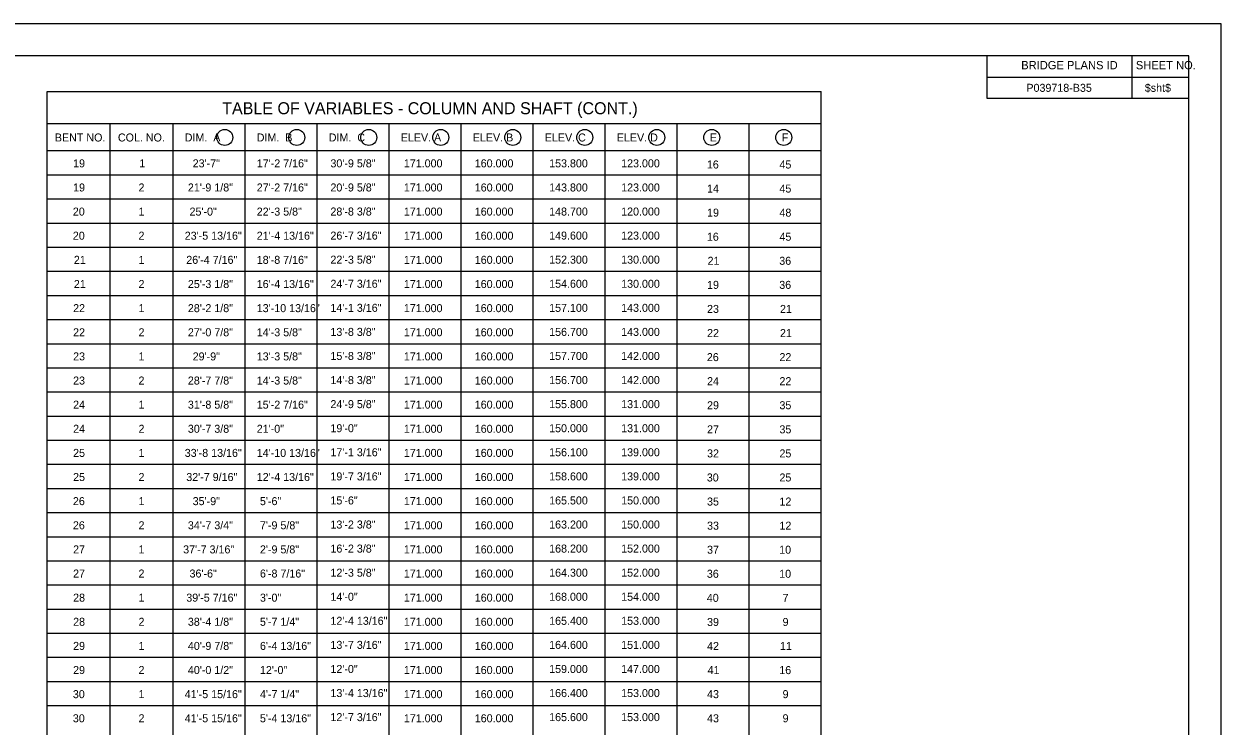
# Model space of a CAD drawing. Extents: x -133.1 to -97, y -1.7 to 20.3.
# Drawn here: x -115.84 to -97.14, y 9.34 to 20.31 of the extents above; entities that cross this region are included whole.
import ezdxf

# ---------------------------------------------------------------- set-up
doc = ezdxf.new("R2010")
doc.units = 0
for name, color, linetype in [('BR_BORDER LINES', 7, 'Continuous'), ('BR_TABLE LINES', 7, 'Continuous'), ('BR_TEXT', 7, 'Continuous'), ('Level 31', 7, 'Continuous')]:
    doc.layers.add(name, color=color, linetype=linetype)

msp = doc.modelspace()

# ---------------------------------------------------------------- linework, layer by layer
at = {"layer": 'BR_BORDER LINES'}
for p, q in [((-97.642, 19.809), (-131.308, 19.809)), ((-100.794, 19.142), (-100.794, 19.809)), ((-98.528, 19.142), (-98.528, 19.809)), ((-97.642, -1.191), (-97.642, 19.809)), ((-100.794, 19.479), (-97.642, 19.479)), ((-98.528, 19.479), (-97.642, 19.479)), ((-97.642, 19.142), (-100.794, 19.142))]:
    msp.add_line(p, q, dxfattribs=at)
at = {"layer": 'BR_TABLE LINES'}
for p, q in [((-115.482, 4.001), (-115.482, 19.253)), ((-115.482, 19.253), (-103.387, 19.253)), ((-103.387, 4.001), (-103.387, 19.253)), ((-115.482, 18.753), (-103.387, 18.753)), ((-114.497, 4.001), (-114.497, 18.753)), ((-113.512, 4.001), (-113.512, 18.753)), ((-112.387, 4.001), (-112.387, 18.753)), ((-111.262, 4.001), (-111.262, 18.753)), ((-110.137, 4.001), (-110.137, 18.753)), ((-109.012, 4.001), (-109.012, 18.753)), ((-107.887, 4.001), (-107.887, 18.753)), ((-106.762, 4.001), (-106.762, 18.753)), ((-105.637, 4.001), (-105.637, 18.753)), ((-104.512, 4.001), (-104.512, 18.753)), ((-115.482, 18.329), (-103.387, 18.329)), ((-115.482, 17.951), (-103.387, 17.951)), ((-115.482, 17.574), (-103.387, 17.574)), ((-115.482, 17.197), (-103.387, 17.197)), ((-115.482, 16.82), (-103.387, 16.82)), ((-115.482, 16.443), (-103.387, 16.443)), ((-115.482, 16.066), (-103.387, 16.066)), ((-115.482, 15.689), (-103.387, 15.689)), ((-115.482, 15.312), (-103.387, 15.312)), ((-115.482, 14.935), (-103.387, 14.935)), ((-115.482, 14.558), (-103.387, 14.558)), ((-115.482, 14.181), (-103.387, 14.181)), ((-115.482, 13.804), (-103.387, 13.804)), ((-115.482, 13.427), (-103.387, 13.427)), ((-115.482, 13.05), (-103.387, 13.05)), ((-115.482, 12.673), (-103.387, 12.673)), ((-115.482, 12.296), (-103.387, 12.296)), ((-115.482, 11.919), (-103.387, 11.919)), ((-115.482, 11.542), (-103.387, 11.542)), ((-115.482, 11.165), (-103.387, 11.165)), ((-115.482, 10.788), (-103.387, 10.788)), ((-115.482, 10.411), (-103.387, 10.411)), ((-115.482, 10.034), (-103.387, 10.034)), ((-115.482, 9.657), (-103.387, 9.657))]:
    msp.add_line(p, q, dxfattribs=at)
at = {"layer": 'BR_TEXT'}
for centre in [(-112.706, 18.535), (-111.581, 18.535), (-110.456, 18.535), (-109.331, 18.535), (-108.206, 18.535), (-107.081, 18.535), (-105.956, 18.535), (-105.097, 18.535), (-103.972, 18.535)]:
    msp.add_circle(centre, 0.125, dxfattribs=at)
at = {"layer": 'Level 31'}
msp.add_lwpolyline([(-133.141, -1.691), (-97.141, -1.691), (-97.141, 20.309), (-133.141, 20.309)], close=True, dxfattribs=at)

# ---------------------------------------------------------------- texts
at = {"layer": 'BR_TEXT'}
for s, height, p in [('BRIDGE PLANS ID', 0.13, (-100.263, 19.6)), ('SHEET NO.', 0.13, (-98.472, 19.6)), ('P039718-B35', 0.125, (-100.182, 19.248)), ('$sht$', 0.125, (-98.332, 19.248)), ('TABLE OF VARIABLES - COLUMN AND SHAFT (CONT.)', 0.1875, (-112.746, 18.898))]:
    msp.add_text(s, height=height, dxfattribs=at).set_placement(p)
for s, p in [('BENT NO.', (-115.36, 18.472)), ('COL. NO.', (-114.375, 18.472)), ('DIM.  A', (-113.331, 18.472)), ('DIM.  B', (-112.206, 18.472)), ('DIM.  C', (-111.081, 18.472)), ('ELEV. A', (-109.956, 18.472)), ('ELEV. B', (-108.831, 18.472)), ('ELEV. C', (-107.706, 18.472)), ('ELEV. D', (-106.581, 18.472)), ('E', (-105.128, 18.472)), ('F', (-104.003, 18.472)), ('19', (-115.075, 18.068)), ('1', (-114.041, 18.068)), ('23\'-7"', (-113.207, 18.068)), ('17\'-2 7/16"', (-112.206, 18.068)), ('30\'-9 5/8"', (-111.055, 18.068)), ('171.000', (-109.908, 18.068)), ('160.000', (-108.8, 18.068)), ('153.800', (-107.638, 18.068)), ('123.000', (-106.513, 18.068)), ('16', (-105.174, 18.05)), ('45', (-104.04, 18.05)), ('19', (-115.075, 17.691)), ('2', (-114.053, 17.691)), ('21\'-9 1/8"', (-113.282, 17.691)), ('27\'-2 7/16"', (-112.206, 17.691)), ('20\'-9 5/8"', (-111.055, 17.691)), ('171.000', (-109.908, 17.691)), ('160.000', (-108.8, 17.691)), ('143.800', (-107.638, 17.691)), ('123.000', (-106.513, 17.691)), ('14', (-105.171, 17.674)), ('45', (-104.04, 17.674)), ('20', (-115.079, 17.314)), ('1', (-114.053, 17.314)), ('25\'-0"', (-113.256, 17.314)), ('22\'-3 5/8"', (-112.206, 17.314)), ('28\'-8 3/8"', (-111.055, 17.315)), ('171.000', (-109.908, 17.314)), ('160.000', (-108.8, 17.314)), ('148.700', (-107.638, 17.315)), ('120.000', (-106.513, 17.315)), ('19', (-105.171, 17.298)), ('48', (-104.04, 17.298)), ('20', (-115.079, 16.937)), ('2', (-114.053, 16.937)), ('23\'-5 13/16"', (-113.331, 16.937)), ('21\'-4 13/16"', (-112.206, 16.937)), ('26\'-7 3/16"', (-111.055, 16.939)), ('171.000', (-109.908, 16.937)), ('160.000', (-108.8, 16.937)), ('149.600', (-107.638, 16.939)), ('123.000', (-106.513, 16.939)), ('16', (-105.174, 16.921)), ('45', (-104.04, 16.921)), ('21', (-115.063, 16.56)), ('1', (-114.053, 16.56)), ('26\'-4 7/16"', (-113.307, 16.56)), ('18\'-8 7/16"', (-112.206, 16.56)), ('22\'-3 5/8"', (-111.055, 16.563)), ('171.000', (-109.908, 16.56)), ('160.000', (-108.8, 16.56)), ('152.300', (-107.638, 16.563)), ('130.000', (-106.513, 16.563)), ('21', (-105.163, 16.545)), ('36', (-104.043, 16.545)), ('21', (-115.063, 16.182)), ('2', (-114.053, 16.182)), ('25\'-3 1/8"', (-113.282, 16.182)), ('16\'-4 13/16"', (-112.206, 16.182)), ('24\'-7 3/16"', (-111.055, 16.186)), ('171.000', (-109.908, 16.182)), ('160.000', (-108.8, 16.182)), ('154.600', (-107.638, 16.186)), ('130.000', (-106.513, 16.186)), ('19', (-105.171, 16.169)), ('36', (-104.043, 16.169)), ('22', (-115.075, 15.805)), ('1', (-114.053, 15.805)), ('28\'-2 1/8"', (-113.282, 15.805)), ('13\'-10 13/16"', (-112.206, 15.805)), ('14\'-1 3/16"', (-111.055, 15.81)), ('171.000', (-109.908, 15.805)), ('160.000', (-108.8, 15.805)), ('157.100', (-107.638, 15.81)), ('143.000', (-106.513, 15.81)), ('23', (-105.171, 15.793)), ('21', (-104.032, 15.793)), ('22', (-115.075, 15.428)), ('2', (-114.053, 15.428)), ('27\'-0 7/8"', (-113.282, 15.428)), ('14\'-3 5/8"', (-112.206, 15.428)), ('13\'-8 3/8"', (-111.055, 15.434)), ('171.000', (-109.908, 15.428)), ('160.000', (-108.8, 15.428)), ('156.700', (-107.638, 15.434)), ('143.000', (-106.513, 15.434)), ('22', (-105.171, 15.416)), ('21', (-104.032, 15.416)), ('23', (-115.075, 15.051)), ('1', (-114.053, 15.051)), ('29\'-9"', (-113.207, 15.051)), ('13\'-3 5/8"', (-112.206, 15.051)), ('15\'-8 3/8"', (-111.055, 15.058)), ('171.000', (-109.908, 15.051)), ('160.000', (-108.8, 15.051)), ('157.700', (-107.638, 15.058)), ('142.000', (-106.513, 15.058)), ('26', (-105.174, 15.04)), ('22', (-104.04, 15.04)), ('23', (-115.075, 14.674)), ('2', (-114.053, 14.674)), ('28\'-7 7/8"', (-113.282, 14.674)), ('14\'-3 5/8"', (-112.206, 14.674)), ('14\'-8 3/8"', (-111.055, 14.681)), ('171.000', (-109.908, 14.674)), ('160.000', (-108.8, 14.674)), ('156.700', (-107.638, 14.681)), ('142.000', (-106.513, 14.681)), ('24', (-105.171, 14.664)), ('22', (-104.04, 14.664)), ('24', (-115.075, 14.297)), ('1', (-114.053, 14.297)), ('31\'-8 5/8"', (-113.282, 14.297)), ('15\'-2 7/16"', (-112.206, 14.297)), ('24\'-9 5/8"', (-111.055, 14.305)), ('171.000', (-109.908, 14.297)), ('160.000', (-108.8, 14.297)), ('155.800', (-107.638, 14.305)), ('131.000', (-106.513, 14.305)), ('29', (-105.171, 14.288)), ('35', (-104.04, 14.288)), ('24', (-115.075, 13.92)), ('2', (-114.053, 13.92)), ('30\'-7 3/8"', (-113.282, 13.92)), ('21\'-0"', (-112.206, 13.92)), ('19\'-0"', (-111.055, 13.929)), ('171.000', (-109.908, 13.92)), ('160.000', (-108.8, 13.92)), ('150.000', (-107.638, 13.929)), ('131.000', (-106.513, 13.929)), ('27', (-105.171, 13.911)), ('35', (-104.04, 13.911)), ('25', (-115.075, 13.543)), ('1', (-114.053, 13.543)), ('33\'-8 13/16"', (-113.331, 13.543)), ('14\'-10 13/16"', (-112.206, 13.543)), ('17\'-1 3/16"', (-111.055, 13.553)), ('171.000', (-109.908, 13.543)), ('160.000', (-108.8, 13.543)), ('156.100', (-107.638, 13.553)), ('139.000', (-106.513, 13.553)), ('32', (-105.171, 13.535)), ('25', (-104.04, 13.535)), ('25', (-115.075, 13.166)), ('2', (-114.053, 13.166)), ('32\'-7 9/16"', (-113.307, 13.166)), ('12\'-4 13/16"', (-112.206, 13.166)), ('19\'-7 3/16"', (-111.055, 13.176)), ('171.000', (-109.908, 13.166)), ('160.000', (-108.8, 13.166)), ('158.600', (-107.638, 13.176)), ('139.000', (-106.513, 13.176)), ('30', (-105.175, 13.159)), ('25', (-104.04, 13.159)), ('26', (-115.078, 12.789)), ('1', (-114.053, 12.789)), ('35\'-9"', (-113.207, 12.789)), ('5\'-6"', (-112.156, 12.789)), ('15\'-6"', (-111.055, 12.8)), ('171.000', (-109.908, 12.789)), ('160.000', (-108.8, 12.789)), ('165.500', (-107.638, 12.8)), ('150.000', (-106.513, 12.8)), ('35', (-105.171, 12.783)), ('12', (-104.04, 12.783)), ('26', (-115.078, 12.412)), ('2', (-114.053, 12.412)), ('34\'-7 3/4"', (-113.282, 12.412)), ('7\'-9 5/8"', (-112.156, 12.412)), ('13\'-2 3/8"', (-111.055, 12.424)), ('171.000', (-109.908, 12.412)), ('160.000', (-108.8, 12.412)), ('163.200', (-107.638, 12.424)), ('150.000', (-106.513, 12.424)), ('33', (-105.171, 12.406)), ('12', (-104.04, 12.406)), ('27', (-115.075, 12.035)), ('1', (-114.053, 12.035)), ('37\'-7 3/16"', (-113.356, 12.035)), ('2\'-9 5/8"', (-112.156, 12.035)), ('16\'-2 3/8"', (-111.055, 12.048)), ('171.000', (-109.908, 12.035)), ('160.000', (-108.8, 12.035)), ('168.200', (-107.638, 12.048)), ('152.000', (-106.513, 12.048)), ('37', (-105.171, 12.03)), ('10', (-104.044, 12.03)), ('27', (-115.075, 11.658)), ('2', (-114.053, 11.658)), ('36\'-6"', (-113.256, 11.658)), ('6\'-8 7/16"', (-112.156, 11.658)), ('12\'-3 5/8"', (-111.055, 11.671)), ('171.000', (-109.908, 11.658)), ('160.000', (-108.8, 11.658)), ('164.300', (-107.638, 11.671)), ('152.000', (-106.513, 11.671)), ('36', (-105.174, 11.654)), ('10', (-104.044, 11.654)), ('39\'-5 7/16"', (-113.307, 11.281)), ('14\'-0"', (-111.055, 11.295)), ('168.000', (-107.638, 11.295)), ('154.000', (-106.513, 11.295)), ('28', (-115.075, 11.281)), ('1', (-114.053, 11.281)), ('3\'-0"', (-112.156, 11.281)), ('171.000', (-109.908, 11.281)), ('160.000', (-108.8, 11.281)), ('40', (-105.175, 11.278)), ('7', (-103.991, 11.278)), ('38\'-4 1/8"', (-113.282, 10.904)), ('5\'-7 1/4"', (-112.156, 10.904)), ('12\'-4 13/16"', (-111.055, 10.919)), ('165.400', (-107.638, 10.919)), ('153.000', (-106.513, 10.919)), ('28', (-115.075, 10.904)), ('2', (-114.053, 10.904)), ('171.000', (-109.908, 10.904)), ('160.000', (-108.8, 10.904)), ('39', (-105.171, 10.901)), ('9', (-103.991, 10.901)), ('13\'-7 3/16"', (-111.055, 10.543)), ('164.600', (-107.638, 10.543)), ('151.000', (-106.513, 10.543)), ('29', (-115.075, 10.527)), ('1', (-114.053, 10.527)), ('40\'-9 7/8"', (-113.282, 10.527)), ('6\'-4 13/16"', (-112.156, 10.527)), ('171.000', (-109.908, 10.527)), ('160.000', (-108.8, 10.527)), ('42', (-105.171, 10.525)), ('11', (-104.032, 10.525)), ('12\'-0"', (-111.055, 10.166)), ('159.000', (-107.638, 10.166)), ('147.000', (-106.513, 10.166)), ('29', (-115.075, 10.15)), ('2', (-114.053, 10.15)), ('40\'-0 1/2"', (-113.282, 10.15)), ('12\'-0"', (-112.156, 10.15)), ('171.000', (-109.908, 10.15)), ('160.000', (-108.8, 10.15)), ('41', (-105.163, 10.149)), ('16', (-104.043, 10.149)), ('13\'-4 13/16"', (-111.055, 9.79)), ('166.400', (-107.638, 9.79)), ('153.000', (-106.513, 9.79)), ('30', (-115.079, 9.773)), ('1', (-114.053, 9.773)), ('41\'-5 15/16"', (-113.331, 9.773)), ('4\'-7 1/4"', (-112.156, 9.773)), ('171.000', (-109.908, 9.773)), ('160.000', (-108.8, 9.773)), ('43', (-105.171, 9.773)), ('9', (-103.991, 9.773)), ('12\'-7 3/16"', (-111.055, 9.414)), ('165.600', (-107.638, 9.414)), ('153.000', (-106.513, 9.414)), ('30', (-115.079, 9.396)), ('2', (-114.053, 9.396)), ('41\'-5 15/16"', (-113.331, 9.396)), ('5\'-4 13/16"', (-112.156, 9.396)), ('171.000', (-109.908, 9.396)), ('160.000', (-108.8, 9.396)), ('43', (-105.171, 9.396)), ('9', (-103.991, 9.396))]:
    msp.add_text(s, height=0.125, rotation=360, dxfattribs=at).set_placement(p)

doc.saveas('drawing.dxf')
